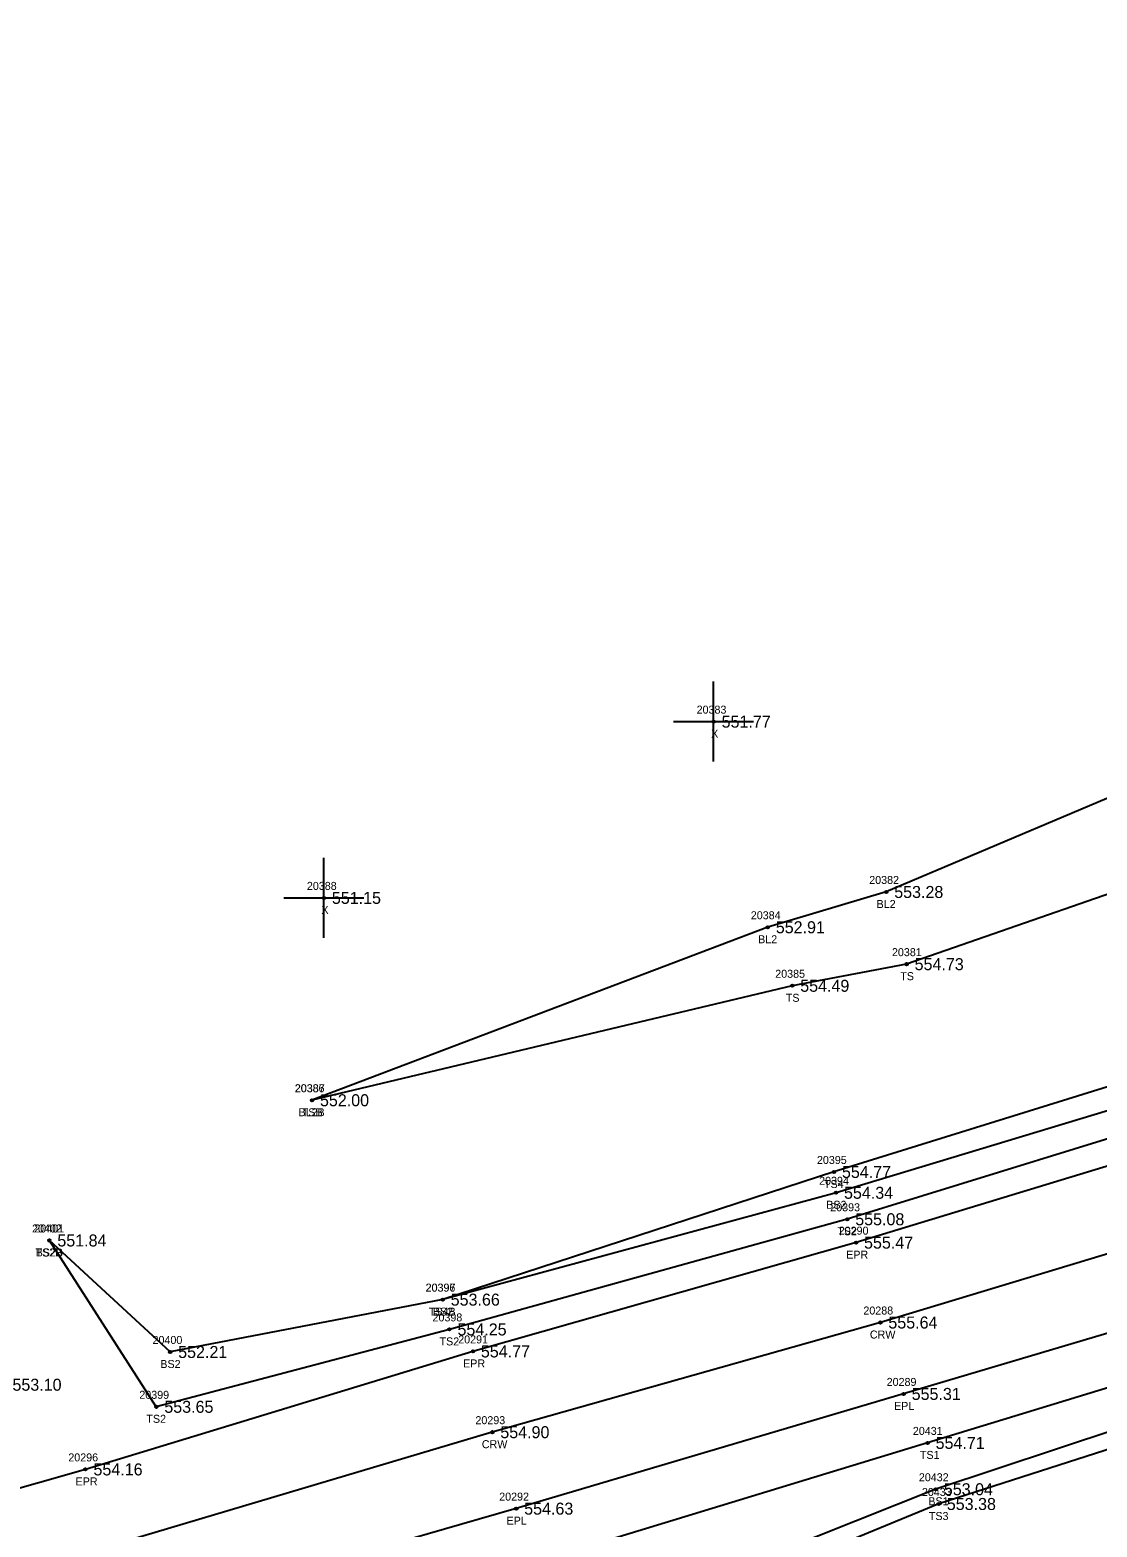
# Model space of a CAD drawing. Extents: x 1540443 to 1541844, y 887157 to 888162.
# Drawn here: x 1541377.9 to 1541511.2, y 887753.4 to 887940.4 of the extents above; entities that cross this region are included whole.
import ezdxf

# ---------------------------------------------------------------- set-up
doc = ezdxf.new("R2010")
doc.units = 0
for name, color, linetype in [('RD_DTM_BkLn1', 7, 'Continuous'), ('RD_DTM_BkLn2', 7, 'Continuous'), ('RD_DTM_BkLn_txCode', 7, 'Continuous'), ('RD_EX_Misc', 7, 'Continuous'), ('RD_EX_Misc_txCode', 7, 'Continuous'), ('RD_EX_Road', 7, 'Continuous'), ('RD_EX_Road_txCode', 7, 'Continuous'), ('RD_EX_TX_Misc_ELEV', 7, 'Continuous'), ('RD_EX_TX_Road_ELEV', 7, 'Continuous'), ('RD_HC_Survey_ELEV', 7, 'Continuous'), ('RD_HC_Survey_txCode', 7, 'Continuous'), ('RD_SMD_Locator', 7, 'Continuous')]:
    doc.layers.add(name, color=color, linetype=linetype)

msp = doc.modelspace()

# ---------------------------------------------------------------- linework, layer by layer
at = {"layer": 'RD_DTM_BkLn1'}
for points in [[(1541819.64, 887879.04), (1541771.84, 887865.01), (1541723.55, 887850.95), (1541675.82, 887836.26), (1541627.89, 887822.08), (1541580.01, 887807.87), (1541531.93, 887793.38), (1541484.13, 887778.91), (1541435.66, 887765.21), (1541388.1, 887751.04), (1541339.55, 887736.89), (1541291.46, 887723.08), (1541243.5, 887708.82), (1541195.27, 887694.78), (1541169.43, 887686.85)], [(1541615.37, 887862.76), (1541586.73, 887853.17), (1541553.55, 887853.3), (1541521.88, 887848.39), (1541484.86, 887832.7), (1541470.07, 887828.29), (1541413.13, 887806.68)]]:
    msp.add_lwpolyline(points, dxfattribs=at)
at = {"layer": 'RD_DTM_BkLn2'}
for points in [[(1541705.44, 887940.39), (1541657.38, 887899.47), (1541615.37, 887862.76), (1541586.87, 887843.69), (1541555.2, 887844), (1541525.74, 887837.02), (1541487.41, 887823.68), (1541473.12, 887820.98), (1541413.13, 887806.68)], [(1541814.01, 887898.31), (1541765.45, 887884.36), (1541753.72, 887881.26), (1541715.98, 887870.29), (1541668.78, 887856.47), (1541621.42, 887842.24), (1541577.85, 887827.54), (1541526.45, 887812.7), (1541478.33, 887797.72), (1541429.46, 887781.77)], [(1541814.49, 887896.02), (1541766.25, 887881.48), (1541716.95, 887866.26), (1541670.06, 887852.12), (1541622.59, 887838.05), (1541578.09, 887825.05), (1541526.96, 887809.73), (1541478.59, 887795.12), (1541429.46, 887781.77), (1541395.42, 887775.23), (1541380.33, 887789.16)], [(1541815.05, 887893.63), (1541767.74, 887877.82), (1541717.6, 887864.13), (1541670.44, 887850.43), (1541623.55, 887835.4), (1541578.57, 887823.06), (1541527.24, 887806.39), (1541479.99, 887791.81), (1541430.31, 887778.05), (1541393.69, 887768.38), (1541380.33, 887789.16)], [(1541824.97, 887864.95), (1541773.24, 887848.9), (1541728.33, 887834.59), (1541680.22, 887820.65), (1541632.2, 887806.6), (1541586.15, 887794.2), (1541535.56, 887777.78), (1541490.03, 887763.87), (1541442.11, 887749.28), (1541414.74, 887732.66), (1541394.55, 887728.51), (1541346.01, 887715.56), (1541298.68, 887704.05), (1541256.52, 887687.99), (1541253.67, 887682.12), (1541204.18, 887671.81), (1541185.24, 887668.7), (1541173.43, 887674.53)], [(1541826.01, 887862.16), (1541773.99, 887846.34), (1541729.05, 887832.97), (1541681.03, 887818.46), (1541632.94, 887804.51), (1541587.44, 887789.41), (1541536.78, 887773.27), (1541491.06, 887758.08), (1541445.99, 887740.14), (1541416.24, 887728.45), (1541395.49, 887723.75), (1541347.04, 887711.22), (1541300.85, 887696.02), (1541261.64, 887680.26), (1541255.59, 887675.42), (1541206.42, 887663.07), (1541174, 887652.79)], [(1541826.81, 887859.86), (1541774.16, 887844.66), (1541729.81, 887830.83), (1541681.55, 887816.28), (1541633.12, 887801.68), (1541588.74, 887788.35), (1541537.56, 887771.08), (1541491.43, 887756.24), (1541446.51, 887737.74), (1541416.24, 887728.45)]]:
    msp.add_lwpolyline(points, dxfattribs=at)
at = {"layer": 'RD_EX_Misc'}
for p, q in [((1541463.3, 887848.98), (1541463.3, 887858.98)), ((1541458.3, 887853.98), (1541468.3, 887853.98)), ((1541414.62, 887826.96), (1541414.62, 887836.96)), ((1541409.62, 887831.96), (1541419.62, 887831.96))]:
    msp.add_line(p, q, dxfattribs=at)
at = {"layer": 'RD_EX_Road'}
for points in [[(1541816.45, 887889.18), (1541769.26, 887875.17), (1541720.7, 887860.02), (1541673.15, 887846.35), (1541624.52, 887832.03), (1541577.1, 887817.68), (1541529.45, 887803.59), (1541481.09, 887788.89), (1541433.23, 887775.3), (1541384.84, 887760.56), (1541337.12, 887746.96), (1541288.35, 887732.65), (1541241.37, 887718.72), (1541192.23, 887703.89), (1541166.88, 887695.38)], [(1541823.08, 887870.08), (1541774.23, 887855.6), (1541726.64, 887841.16), (1541678.89, 887827.09), (1541630.15, 887812.57), (1541582.93, 887798.43), (1541534.59, 887784.1), (1541487.04, 887769.99), (1541438.64, 887755.66), (1541391.44, 887742.05), (1541342.36, 887727.48), (1541295.07, 887713.91), (1541246.74, 887699.66), (1541197.81, 887684.79), (1541172.48, 887676.63)]]:
    msp.add_lwpolyline(points, dxfattribs=at)
at = {"layer": 'RD_SMD_Locator'}
for centre in [(1541463.3, 887853.98), (1541414.62, 887831.96), (1541484.86, 887832.7), (1541470.07, 887828.29), (1541487.41, 887823.68), (1541473.12, 887820.98), (1541413.13, 887806.68), (1541413.13, 887806.68), (1541478.33, 887797.72), (1541478.59, 887795.12), (1541479.99, 887791.81), (1541380.33, 887789.16), (1541380.33, 887789.16), (1541481.09, 887788.89), (1541429.46, 887781.77), (1541429.46, 887781.77), (1541430.31, 887778.05), (1541484.13, 887778.91), (1541395.42, 887775.23), (1541433.23, 887775.3), (1541487.04, 887769.99), (1541393.69, 887768.38), (1541435.66, 887765.21), (1541490.03, 887763.87), (1541384.84, 887760.56), (1541491.06, 887758.08), (1541438.64, 887755.66), (1541491.43, 887756.24)]:
    msp.add_circle(centre, 0.15, dxfattribs=at)

# ---------------------------------------------------------------- texts
at = {"layer": 'RD_DTM_BkLn_txCode'}
for s, p in [('20382', (1541482.74, 887833.7)), ('BL2', (1541483.66, 887830.7)), ('20384', (1541467.95, 887829.29)), ('BL2', (1541468.86, 887826.29)), ('20381', (1541485.58, 887824.68)), ('20385', (1541471, 887821.98)), ('TS', (1541486.62, 887821.68)), ('TS', (1541472.32, 887818.98)), ('20386', (1541410.98, 887807.68)), ('20387', (1541411.01, 887807.68)), ('BL2B', (1541411.45, 887804.68)), ('TSB', (1541411.86, 887804.68)), ('20395', (1541476.21, 887798.72)), ('20394', (1541476.48, 887796.12)), ('TS4', (1541477.09, 887795.72)), ('BS2', (1541477.37, 887793.12)), ('20393', (1541477.87, 887792.81)), ('20402', (1541378.17, 887790.16)), ('20401', (1541378.45, 887790.16)), ('TS2', (1541478.75, 887789.81)), ('TS2B', (1541378.61, 887787.16)), ('BS2B', (1541378.62, 887787.16)), ('20396', (1541427.32, 887782.77)), ('20397', (1541427.34, 887782.77)), ('TS4B', (1541427.74, 887779.77)), ('20398', (1541428.19, 887779.05)), ('BS2', (1541428.23, 887779.77)), ('20400', (1541393.22, 887776.23)), ('TS2', (1541429.07, 887776.05)), ('BS2', (1541394.19, 887773.23)), ('20399', (1541391.57, 887769.38)), ('TS2', (1541392.45, 887766.38)), ('20431', (1541488.19, 887764.87)), ('TS1', (1541489.07, 887761.87)), ('20432', (1541488.94, 887759.08)), ('20433', (1541489.32, 887757.24)), ('BS1', (1541490.12, 887756.08)), ('TS3', (1541490.19, 887754.24))]:
    msp.add_text(s, height=1, dxfattribs=at).set_placement(p)
at = {"layer": 'RD_EX_Misc_txCode'}
for s, p in [('20383', (1541461.18, 887854.98)), ('X', (1541462.99, 887851.98)), ('20388', (1541412.5, 887832.96)), ('X', (1541414.31, 887829.96))]:
    msp.add_text(s, height=1, dxfattribs=at).set_placement(p)
at = {"layer": 'RD_EX_Road_txCode'}
for s, p in [('20290', (1541478.93, 887789.89)), ('EPR', (1541479.86, 887786.89)), ('20291', (1541431.4, 887776.3)), ('EPR', (1541432.01, 887773.3)), ('20289', (1541484.92, 887770.99)), ('EPL', (1541485.84, 887767.99)), ('20296', (1541382.7, 887761.56)), ('EPR', (1541383.61, 887758.56)), ('20292', (1541436.52, 887756.66)), ('EPL', (1541437.44, 887753.66))]:
    msp.add_text(s, height=1, dxfattribs=at).set_placement(p)
at = {"layer": 'RD_EX_TX_Misc_ELEV'}
for s, p in [('551.77', (1541464.3, 887853.23)), ('553.28', (1541485.86, 887831.95)), ('551.15', (1541415.62, 887831.21)), ('552.91', (1541471.07, 887827.54)), ('554.73', (1541488.41, 887822.93)), ('554.49', (1541474.12, 887820.23)), ('552.00', (1541414.13, 887805.93)), ('552.00', (1541414.13, 887805.93)), ('554.77', (1541479.33, 887796.97)), ('554.34', (1541479.59, 887794.37)), ('555.08', (1541480.99, 887791.06)), ('551.84', (1541381.33, 887788.41)), ('551.84', (1541381.33, 887788.41)), ('553.66', (1541430.46, 887781.02)), ('553.66', (1541430.46, 887781.02)), ('554.25', (1541431.31, 887777.3)), ('552.21', (1541396.42, 887774.48)), ('553.10', (1541375.72, 887770.39)), ('553.65', (1541394.69, 887767.63)), ('554.71', (1541491.03, 887763.12)), ('553.04', (1541492.06, 887757.33)), ('553.38', (1541492.43, 887755.49))]:
    msp.add_text(s, height=1.5, dxfattribs=at).set_placement(p)
at = {"layer": 'RD_EX_TX_Road_ELEV'}
for s, p in [('555.47', (1541482.09, 887788.14)), ('554.77', (1541434.23, 887774.55)), ('555.31', (1541488.04, 887769.24)), ('554.16', (1541385.84, 887759.81)), ('554.63', (1541439.64, 887754.91))]:
    msp.add_text(s, height=1.5, dxfattribs=at).set_placement(p)
at = {"layer": 'RD_HC_Survey_ELEV'}
for s, p in [('555.64', (1541485.13, 887778.16)), ('554.90', (1541436.66, 887764.46))]:
    msp.add_text(s, height=1.5, dxfattribs=at).set_placement(p)
at = {"layer": 'RD_HC_Survey_txCode'}
for s, p in [('20288', (1541482.01, 887779.91)), ('CRW', (1541482.82, 887776.91)), ('20293', (1541433.55, 887766.21)), ('CRW', (1541434.35, 887763.21))]:
    msp.add_text(s, height=1, dxfattribs=at).set_placement(p)

doc.saveas('drawing.dxf')
